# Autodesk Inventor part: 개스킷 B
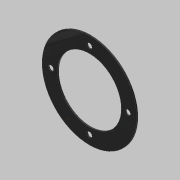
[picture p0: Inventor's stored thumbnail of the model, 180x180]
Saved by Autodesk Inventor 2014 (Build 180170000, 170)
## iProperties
Created: 2019-10
Part Number: 개스킷 B
Material: 고무
Document SubType Name: Modeling
Designer: mduedu
Density: 0.93 g/cm^3
Appearance: Rubber - Black - Version 1.1
Mass: 2.48562 g
Surface Area: 58.2294 cm^2
Volume: 2.67271 cm^3
Author: mduedu
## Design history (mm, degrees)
sketch "스케치1"
  geometry: C1 r 40 at (0, 0); C2 r 27 at (0, 0); 1 further point
  constraints: 2 centre point, 2 coincident
  dimensions: "d0" = 80 diameter of C1; "d1" = 54 diameter of C2
extrude "돌출1" new body sketch "스케치1" distance "d2" = 1; taper "d3" = 0 deg
sketch "스케치2" dims "d4" = 65
  geometry: C1 r 2.25 at (0, 32.5); 2 further points
  constraints: 2 vertical alignment, 1 centre point, 1 coincident, 2 other
  dimensions: "d5" = 4.5 diameter of C1
extrude "돌출2" cut sketch "스케치2" stored distance "d6" = 1; taper "d7" = 0 deg
node "솔리드1"
pattern_circular "원형 패턴1" dims angle "d9" = 360 deg
